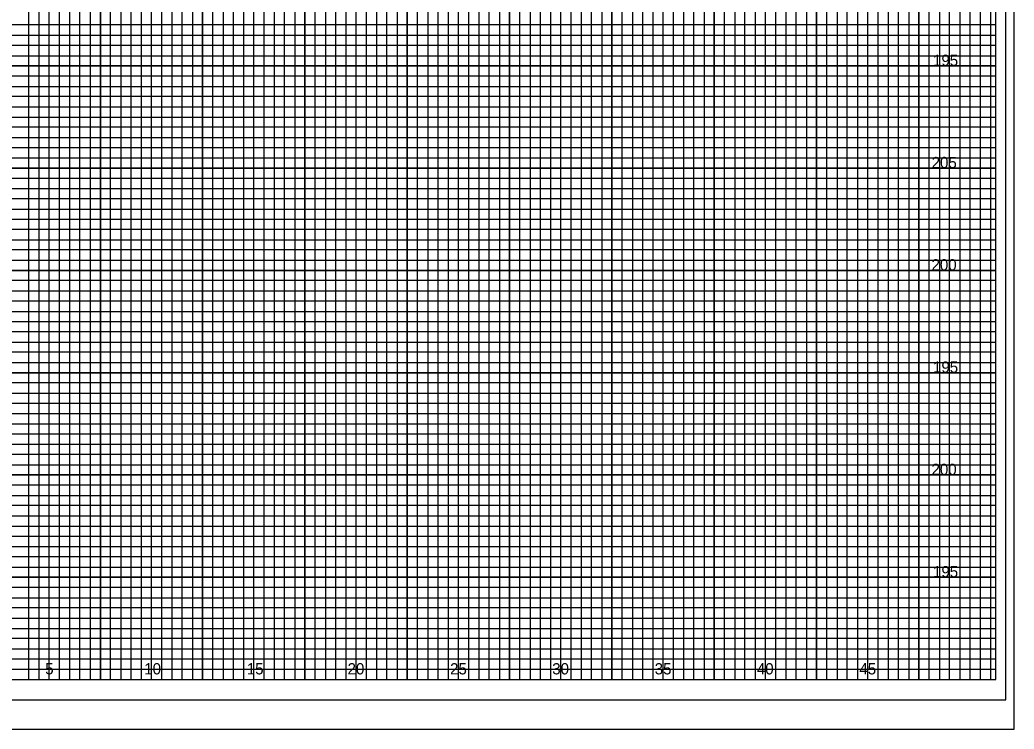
# Model space of a CAD drawing. Extents: x -4 to 103, y -2 to 209.
# Drawn here: x 54.82 to 103.4, y -2.43 to 32.25 of the extents above; entities that cross this region are included whole.
import ezdxf

# ---------------------------------------------------------------- set-up
doc = ezdxf.new("R2010")
doc.units = 0
for name, color, linetype in [('Exist XS Ground Line', 7, 'Continuous'), ('Old_Level_10', 7, 'Continuous'), ('Old_Level_16', 7, 'Continuous'), ('Old_Level_3', 7, 'Continuous'), ('Old_Level_5', 7, 'Continuous'), ('Old_Level_8', 7, 'Continuous'), ('Prop XS Finish Grade Earthwork', 7, 'Continuous'), ('Prop XS Finish Grade Pavement', 7, 'Continuous'), ('Prop XS SE Text', 7, 'Continuous')]:
    doc.layers.add(name, color=color, linetype=linetype)

msp = doc.modelspace()

# ---------------------------------------------------------------- linework, layer by layer
at = {"layer": 'Exist XS Ground Line'}
msp.add_lwpolyline([(103, 66), (-2.8, 66), (-2.8, -1), (103, -1)], close=True, dxfattribs=at)
at = {"layer": 'Old_Level_10'}
for p, q in [((56.25, 0), (56.25, 65)), ((58.75, 0), (58.75, 65)), ((61.25, 0), (61.25, 65)), ((63.75, 0), (63.75, 65)), ((66.25, 0), (66.25, 65)), ((68.75, 0), (68.75, 65)), ((71.25, 0), (71.25, 65)), ((73.75, 0), (73.75, 65)), ((91.25, 0), (91.25, 63.425)), ((93.75, 0), (93.75, 63.425)), ((96.25, 0), (96.25, 63.425)), ((98.75, 0), (98.75, 63.425)), ((101.25, 0), (101.25, 63.425)), ((76.25, 0), (76.25, 62)), ((78.75, 0), (78.75, 62)), ((81.25, 0), (81.25, 62)), ((83.75, 0), (83.75, 62)), ((86.25, 0), (86.25, 62)), ((88.75, 0), (88.75, 62)), ((0, 30), (102.5, 30)), ((0, 27.5), (102.5, 27.5)), ((0, 25), (102.5, 25)), ((0, 22.5), (102.5, 22.5)), ((0, 20), (102.5, 20)), ((0, 17.5), (102.5, 17.5)), ((0, 15), (102.5, 15)), ((0, 12.5), (102.5, 12.5)), ((0, 10), (102.5, 10)), ((0, 7.5), (102.5, 7.5)), ((0, 5), (102.5, 5)), ((0, 2.5), (102.5, 2.5))]:
    msp.add_line(p, q, dxfattribs=at)
at = {"layer": 'Old_Level_3'}
msp.add_line((-3.5, -2.425), (103.4, -2.425), dxfattribs=at)
at = {"layer": 'Old_Level_5'}
msp.add_lwpolyline([(103.4, 67.4), (-3.5, 67.4), (-3.5, -2.425), (103.4, -2.425)], close=True, dxfattribs=at)
at = {"layer": 'Old_Level_8'}
for points in [[(56.25, 0), (56.25, 65)], [(58.75, 65), (58.75, 0), (61.25, 0), (61.25, 65)], [(63.75, 65), (63.75, 0), (66.25, 0), (66.25, 65)], [(68.75, 65), (68.75, 0), (71.25, 0), (71.25, 65)], [(73.75, 65), (73.75, 0), (76.25, 0), (76.25, 62)], [(88.75, 62), (88.75, 0), (91.25, 0), (91.25, 63.425)], [(93.75, 63.425), (93.75, 0), (96.25, 0), (96.25, 63.425)], [(98.75, 63.425), (98.75, 0), (101.25, 0), (101.25, 63.425)], [(78.75, 62), (78.75, 0), (81.25, 0), (81.25, 62)], [(83.75, 62), (83.75, 0), (86.25, 0), (86.25, 62)], [(0, 27.5), (102.5, 27.5), (102.5, 30), (0, 30)], [(0, 22.5), (102.5, 22.5), (102.5, 25), (0, 25)], [(0, 17.5), (102.5, 17.5), (102.5, 20), (0, 20)], [(0, 12.5), (102.5, 12.5), (102.5, 15), (0, 15)], [(0, 7.5), (102.5, 7.5), (102.5, 10), (0, 10)], [(0, 2.5), (102.5, 2.5), (102.5, 5), (0, 5)]]:
    msp.add_lwpolyline(points, dxfattribs=at)
at = {"layer": 'Prop XS Finish Grade Earthwork'}
for points in [[(54.75, 0), (55.25, 0), (55.25, 65)], [(55.75, 65), (55.75, 0), (56.75, 0), (56.75, 65)], [(57.25, 65), (57.25, 0), (57.75, 0), (57.75, 65)], [(58.25, 65), (58.25, 0), (59.25, 0), (59.25, 65)], [(59.75, 65), (59.75, 0), (60.25, 0), (60.25, 65)], [(60.75, 65), (60.75, 0), (61.75, 0), (61.75, 65)], [(62.25, 65), (62.25, 0), (62.75, 0), (62.75, 65)], [(63.25, 65), (63.25, 0), (64.25, 0), (64.25, 65)], [(64.75, 65), (64.75, 0), (65.25, 0), (65.25, 65)], [(65.75, 65), (65.75, 0), (66.75, 0), (66.75, 65)], [(67.25, 65), (67.25, 0), (67.75, 0), (67.75, 65)], [(68.25, 65), (68.25, 0), (69.25, 0), (69.25, 65)], [(69.75, 65), (69.75, 0), (70.25, 0), (70.25, 65)], [(70.75, 65), (70.75, 0), (71.75, 0), (71.75, 65)], [(72.25, 65), (72.25, 0), (72.75, 0), (72.75, 65)], [(73.25, 65), (73.25, 0), (74.25, 0), (74.25, 62)], [(89.75, 62), (89.75, 0), (90.25, 0), (90.25, 63.425)], [(90.75, 63.425), (90.75, 0), (91.75, 0), (91.75, 63.425)], [(92.25, 63.425), (92.25, 0), (92.75, 0), (92.75, 63.425)], [(93.25, 63.425), (93.25, 0), (94.25, 0), (94.25, 63.425)], [(94.75, 63.425), (94.75, 0), (95.25, 0), (95.25, 63.425)], [(95.75, 63.425), (95.75, 0), (96.75, 0), (96.75, 63.425)], [(97.25, 63.425), (97.25, 0), (97.75, 0), (97.75, 63.425)], [(98.25, 63.425), (98.25, 0), (99.25, 0), (99.25, 63.425)], [(99.75, 63.425), (99.75, 0), (100.25, 0), (100.25, 63.425)], [(100.25, 63.425), (100.75, 63.425), (100.75, 0), (101.75, 0), (101.75, 63.425), (102.25, 63.425), (102.25, 0)], [(74.75, 62), (74.75, 0), (75.25, 0), (75.25, 62)], [(75.75, 62), (75.75, 0), (76.75, 0), (76.75, 62)], [(77.25, 62), (77.25, 0), (77.75, 0), (77.75, 62)], [(78.25, 62), (78.25, 0), (79.25, 0), (79.25, 62)], [(79.75, 62), (79.75, 0), (80.25, 0), (80.25, 62)], [(80.75, 62), (80.75, 0), (81.75, 0), (81.75, 62)], [(82.25, 62), (82.25, 0), (82.75, 0), (82.75, 62)], [(83.25, 62), (83.25, 0), (84.25, 0), (84.25, 62)], [(84.75, 62), (84.75, 0), (85.25, 0), (85.25, 62)], [(85.75, 62), (85.75, 0), (86.75, 0), (86.75, 62)], [(87.25, 62), (87.25, 0), (87.75, 0), (87.75, 62)], [(88.25, 62), (88.25, 0), (89.25, 0), (89.25, 62)], [(0, 31.5), (102.5, 31.5), (102.5, 32), (0, 32)], [(0, 30.5), (102.5, 30.5), (102.5, 31), (0, 31)], [(0, 29), (102.5, 29), (102.5, 29.5), (0, 29.5)], [(0, 28), (102.5, 28), (102.5, 28.5), (0, 28.5)], [(0, 26.5), (102.5, 26.5), (102.5, 27), (0, 27)], [(0, 25.5), (102.5, 25.5), (102.5, 26), (0, 26)], [(0, 24), (102.5, 24), (102.5, 24.5), (0, 24.5)], [(0, 23), (102.5, 23), (102.5, 23.5), (0, 23.5)], [(0, 21.5), (102.5, 21.5), (102.5, 22), (0, 22)], [(0, 20.5), (102.5, 20.5), (102.5, 21), (0, 21)], [(0, 19), (102.5, 19), (102.5, 19.5), (0, 19.5)], [(0, 18), (102.5, 18), (102.5, 18.5), (0, 18.5)], [(0, 16.5), (102.5, 16.5), (102.5, 17), (0, 17)], [(0, 15.5), (102.5, 15.5), (102.5, 16), (0, 16)], [(0, 14), (102.5, 14), (102.5, 14.5), (0, 14.5)], [(0, 13), (102.5, 13), (102.5, 13.5), (0, 13.5)], [(0, 11.5), (102.5, 11.5), (102.5, 12), (0, 12)], [(0, 10.5), (102.5, 10.5), (102.5, 11), (0, 11)], [(0, 9), (102.5, 9), (102.5, 9.5), (0, 9.5)], [(0, 8), (102.5, 8), (102.5, 8.5), (0, 8.5)], [(0, 6.5), (102.5, 6.5), (102.5, 7), (0, 7)], [(0, 5.5), (102.5, 5.5), (102.5, 6), (0, 6)], [(0, 4), (102.5, 4), (102.5, 4.5), (0, 4.5)], [(0, 3), (102.5, 3), (102.5, 3.5), (0, 3.5)], [(0, 1.5), (102.5, 1.5), (102.5, 2), (0, 2)], [(0, 0.5), (102.5, 0.5), (102.5, 1), (0, 1)]]:
    msp.add_lwpolyline(points, dxfattribs=at)
at = {"layer": 'Prop XS SE Text'}
msp.add_lwpolyline([(102.5, 65), (0, 65), (0, 0), (102.5, 0)], close=True, dxfattribs=at)

# ---------------------------------------------------------------- texts
at = {"layer": 'Old_Level_16'}
for s, p in [('5', (56.057, 0.25)), ('10', (60.897, 0.25)), ('15', (65.906, 0.25)), ('20', (70.831, 0.25)), ('25', (75.84, 0.25)), ('30', (80.831, 0.25)), ('35', (85.84, 0.25)), ('40', (90.831, 0.25)), ('45', (95.84, 0.25))]:
    msp.add_text(s, height=0.55, dxfattribs=at).set_placement(p)
at = {"layer": 'Prop XS Finish Grade Pavement'}
for s, p in [('195', (99.438, 30)), ('205', (99.372, 25)), ('200', (99.364, 20)), ('195', (99.438, 15)), ('200', (99.364, 10)), ('195', (99.438, 5))]:
    msp.add_text(s, height=0.55, dxfattribs=at).set_placement(p)

doc.saveas('drawing.dxf')
